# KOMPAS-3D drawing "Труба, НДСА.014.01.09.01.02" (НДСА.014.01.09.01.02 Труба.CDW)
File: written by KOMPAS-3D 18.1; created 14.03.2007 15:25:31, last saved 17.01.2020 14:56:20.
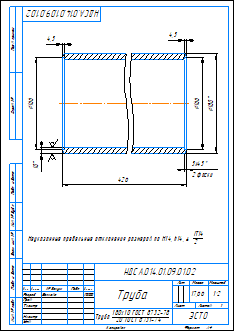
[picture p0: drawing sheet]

Sheet 1: A4, portrait

Document properties: Автор: Устинов А.В.; Организация: Эсто-вакуум; Полное имя файла: НДСА.014.01.09.01.02 Труба.m3d; PDM_DOCXDTO: <item xmlns="http://appius.ru/pdm" xmlns:xs="http://www.w3.org/2001/XMLSchema" xmlns:xsi="http://www.w3.org/2001/XMLSchema-instance" xsi:type="item">  <element xmlns:d2p1="http://v8.1c.ru/8.1/data/enterprise/current-config" xsi:type="d2p1:CatalogRef.aps_Элемен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; Масса: 17.6626

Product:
- Part/product: Труба  | designation НДСА.014.01.09.01.02
    Материал: Труба$d180х10 ГОСТ 8732-78;20 ГОСТ 8731-74$ (density 7859 kg/m3)
    Масса: 17.6626

Title block, sheet 1: Наименование: Труба; designation: НДСА.014.01.09.01.02; Материал: Труба 180х10 ГОСТ 8732-78 20 ГОСТ 8731-74; Масса: 17,66; scale: 1:2; Количество листов документа: 1; organisation: ЭСТО; Форматы листов документа: A4; stored path: D:\Шлейф\УКРД.762.10.00.00.00 Верхняя стойка\УКРД.762.10.01.00.03 Труба.cdw; Разработал: Волкова; Разработал, date: 17.01.2020
Table, sheet 1:
  0;Material:V399CD8922A934364BF9D3DB1A16B3F75;Sortament:VACA86AD6B524487FA06521D22EE88F1C^SortamentEx:VA444AFA89AC74945B3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

Views: Вид 1, Сверху, Разрез А-А
Referenced files in E:\НДСА.014.01.09.00.00 Верхняя стойка гидроподъемника\: НДСА.014.01.09.01.02 Труба.m3d
Dimensions and other numbers on the sheet: 180; 166; 10; 426; 5; 2 фаски; 4,5; 1:2; 1; 17,66; 17.01.2020

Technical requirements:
  Неуказанные предельные отклонения размеров по H14, h14,    IT14 2 .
